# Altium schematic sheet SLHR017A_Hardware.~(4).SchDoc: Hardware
size 431 x 279 mm; Date: Not shown in title block; ApprovedBy: Not shown in title block; CheckedBy: Not shown in title block; Author: Not shown in title block; CompanyName: Not shown in title block; DrawnBy: Kirby Kruckmeyer; Engineer: Not shown in title block; Organization: Not shown in title block; Address1: Not shown in title block; Address2: Not shown in title block; Address3: Not shown in title block; Address4: Not shown in title block; DocumentNumber: 2; Revision: Use project parameter SCH_Rev; SheetNumber: 2; SheetTotal: 2; PageSetup: Record=PageOptions¦CenterHorizontal=True¦CenterVertical=True¦PrintScale=1.00¦XCorrection=1.00¦YCorrection=1.00¦PrintKind=0¦BorderSize=5000000¦LeftOffset=0¦BottomOffset=0¦Orientation=2¦PaperLength=1000¦PaperWidth=1000¦Scale=100¦PaperSource=15¦PrintQuality=600¦MediaType=1¦DitherType=10¦PaperKind=Letter¦PrintScaleMode=1
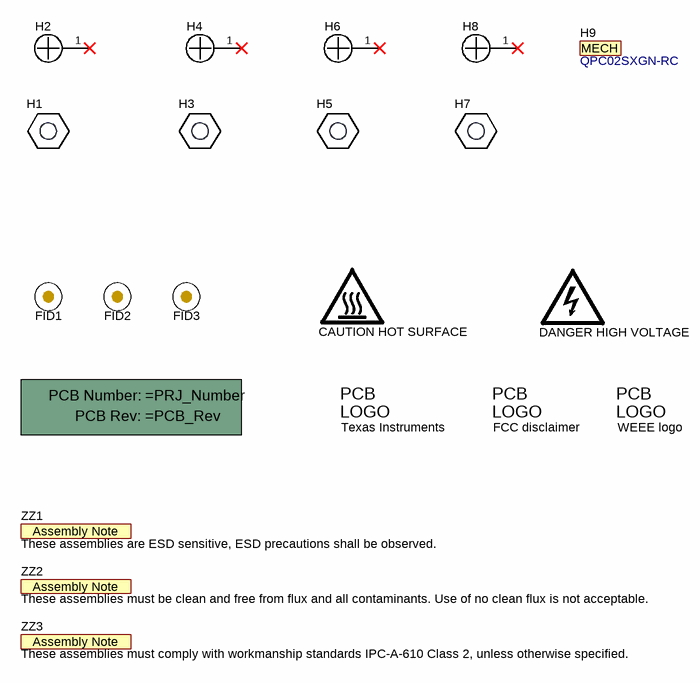
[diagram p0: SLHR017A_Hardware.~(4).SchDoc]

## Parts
!PCB1  Printed Circuit Board  (value not drawn)  (mechanical)
FID1  Fiducial  [Fiducial10-20]  (value not drawn)
FID2  Fiducial  [Fiducial10-20]  (value not drawn)
FID3  Fiducial  [Fiducial10-20]  (value not drawn)
H1  1902C  [Keystone_1902C]  (value not drawn)
H2  NY PMS 440 0025 PH  [NY PMS 440 0025 PH]  (value not drawn)
H3  1902C  [Keystone_1902C]  (value not drawn)
H4  NY PMS 440 0025 PH  [NY PMS 440 0025 PH]  (value not drawn)
H5  1902C  [Keystone_1902C]  (value not drawn)
H6  NY PMS 440 0025 PH  [NY PMS 440 0025 PH]  (value not drawn)
H7  1902C  [Keystone_1902C]  (value not drawn)
H8  NY PMS 440 0025 PH  [NY PMS 440 0025 PH]  (value not drawn)
H9  QPC02SXGN-RC  (mechanical)
LOGO1  CAUTION HOT SURFACE  [IEC_HotSurface_Small]  (no BOM)
Logo2  Texas Instruments  [TI_Stacked_Overlay_Small]  (no BOM)
Logo3  FCC disclaimer  [FCC_disclaimer]  (no BOM)
LOGO4  DANGER HIGH VOLTAGE  [IEC_HighVoltage_Small]  (no BOM)
Logo5  WEEE logo  [WEEE_Minimum]  (no BOM)
ZZ1  These assemblies are ESD sensitive, ESD precautions shall be observed.  [AssemblyNote]  (no BOM)
ZZ2  These assemblies must be clean and free from flux and all contaminants. Use of no clean flux is not acceptable.  [AssemblyNote]  (no BOM)
ZZ3  These assemblies must comply with workmanship standards IPC-A-610 Class 2, unless otherwise specified.  [AssemblyNote]  (no BOM)

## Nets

Not connected (* = marked no-connect by the designer): H2 1*; H4 1*; H6 1*; H8 1*

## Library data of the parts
!PCB1 = CMP-0003618-2: Manufacturer: Any
FID1-FID3 = CMP-0077181-1: Fiducial mark.  There is nothing to buy or mount.
H1 H3 H5 H7 = CMP-0003610-1: Standoff, Hex, 0.5"L #4-40 Nylon; Manufacturer: Keystone; CompType: Hardware
H2 H4 H6 H8 = CMP-0003617-1: Machine Screw, Round, #4-40 x 1/4, Nylon, Philips panhead; Manufacturer: B&F Fastener Supply; CompType: Hardware
H9 = CMP-0080604-2: CONN JUMPER SHORTING .100" GOLD; Manufacturer: Used in BOM report; CompType: Mechanical
LOGO1 = CMP-0074837-1: IEC 61010-1 Hot Surface Warning; SymbolCreator: a0412235; Lib Reference: IEC_HotSurface
Logo2 = CMP-0074838-1: Texas Instrument Corporate Signature; SymbolCreator: a0412235; Lib Reference: TI_Logo; Library Reference: Logo
Logo3 = CMP-0074847-1: FCC_disclaimer; Library Reference: Logo
LOGO4 = CMP-0074835-1: IEC 61010-1 High Voltage Warning; SymbolCreator: a0412235; Lib Reference: IEC_HighVoltage
Logo5 = CMP-0074769-1
ZZ1 = CMP-0077236-1
ZZ2 = CMP-0077237-1
ZZ3 = CMP-0077238-1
